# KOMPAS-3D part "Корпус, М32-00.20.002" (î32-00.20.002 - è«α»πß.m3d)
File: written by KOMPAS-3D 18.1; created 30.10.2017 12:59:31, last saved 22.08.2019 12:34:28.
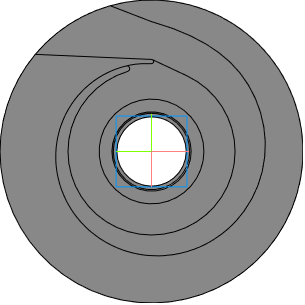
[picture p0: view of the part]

Document properties: Автор: Милов; Организация: Милов; Полное имя файла: D:\Magna\Магна Ins\Магна ins 32\Для Караби Магна 32\М32-00.20.002 - Корпус.m3d

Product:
- Part/product: Корпус  | designation М32-00.20.002  | pos. 0
    Материал: Полипропилен  ГОСТ 26996-86 (density 900 kg/m3)
    Масса: 1.66329
    Раздел спецификации: Детали
    Форматы листов документа: A3
    source file: М32-00.20.002 - Корпус.cdw

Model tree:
1. Эскиз:1
2. Операция выдавливания:1
     Расстояние 1 = 64
3. Эскиз:3  (with: Операция выдавливания:1)
4. Вырезать элемент выдавливания:1
     Расстояние 1 = 50
5. Эскиз:5  (with: Вырезать элемент выдавливания:1)
6. Операция выдавливания:2
     Расстояние 1 = 6.5
7. Эскиз:7  (with: Операция выдавливания:1)
8. Операция выдавливания:3
     Расстояние 1 = 32
9. Фаска:2  (with: Операция выдавливания:2)
     Угол = 45; Длина 1 = 1; Длина 2 = 1
10. Эскиз:13  (with: Операция выдавливания:1)
11. Вырезать элемент выдавливания:3
     Толщина стенки 2 = 5; Расстояние 1 = 5
12. Эскиз:14  (with: Операция выдавливания:3, Вырезать элемент выдавливания:3)
13. Операция выдавливания:6
     Расстояние 1 = 3
14. Эскиз:16  (with: Вырезать элемент выдавливания:3)
15. Операция выдавливания:7  (with: Операция выдавливания:1)
     Расстояние 2 = 59
16. Эскиз:17  (with: Операция выдавливания:1, Операция выдавливания:7, Вырезать элемент выдавливания:1)
17. Вырезать элемент выдавливания:4  (with: Вырезать элемент выдавливания:1)
     Расстояние 1 = 50
18. Скругление:1
     Радиус = 20
19. Эскиз:18  (with: Вырезать элемент выдавливания:3, Операция выдавливания:7)
20. Операция выдавливания:8  (with: Операция выдавливания:6)
     Расстояние 1 = 8
21. Эскиз:20  (with: Операция выдавливания:6, Операция выдавливания:8)
22. Операция выдавливания:10
     Расстояние 1 = 4
23. Эскиз:19  (with: Операция выдавливания:10, Операция выдавливания:3)
24. Операция выдавливания:9
     Расстояние 1 = 8
25. Эскиз:22  (with: Вырезать элемент выдавливания:1, Вырезать элемент выдавливания:4)
26. Операция выдавливания:12  (with: Операция выдавливания:1)
     Расстояние 1 = 50
27. Скругление:2  (with: Вырезать элемент выдавливания:1)
     Радиус = 20
28. Эскиз:24  (with: Вырезать элемент выдавливания:1, Фаска:2)
29. Операция выдавливания:13  (with: Операция выдавливания:2)
     Толщина стенки 1 = 2; Расстояние 1 = 6.5
30. Эскиз:26  (with: Операция выдавливания:2, Операция выдавливания:13)
31. Вырезать элемент выдавливания:6  (with: Эскиз:30, Вырезать элемент выдавливания:1, Операция выдавливания:9)  (labels: Магна Ins 32-L-3(1)-N; Корпус М32\Корпус\Корпус)
     Расстояние 1 = 1.5
32. Вырезать элемент вращения:2  (with: Операция выдавливания:3)
     Угол 1 = 360
33. Вырезать элемент выдавливания:10  (with: Операция выдавливания:9)
     Расстояние 1 = 9
34. Фаска:5  (with: Вырезать элемент выдавливания:10)
     Угол = 45; Длина 1 = 2; Длина 2 = 2
35. Эскиз:31  (with: Вырезать элемент вращения:2, Вырезать элемент выдавливания:10)
36. Элемент выдавливания:1  (with: Операция выдавливания:1)
37. Эскиз:32  (with: Операция выдавливания:1, Элемент выдавливания:1)
38. Элемент выдавливания:2  (with: Вырезать элемент выдавливания:1)
     Расстояние 2 = 50
39. Эскиз:34  (with: Вырезать элемент вращения:2, Элемент выдавливания:1)
40. Элемент выдавливания:3  (with: Операция выдавливания:6)  (labels: ..\М32-00.20.000 - Корпус.a3d; D:\Magna\Магна Ins\Магна ins 32\М32-00.20.000 - Корпус.a3d)
     Расстояние 1 = 6.5
41. Элемент выдавливания:4  (with: Вырезать элемент вращения:2, Вырезать элемент выдавливания:1)
42. Фаска:7  (with: Элемент выдавливания:3, Элемент выдавливания:4, Эскиз:36, Операция выдавливания:1, Операция выдавливания:3)
     Угол = 45; Длина 1 = 2; Длина 2 = 2
43. Элемент выдавливания:5
     Расстояние 2 = 8
44. Фаска:8  (with: Элемент выдавливания:5)
     Угол = 45; Длина 1 = 3; Длина 2 = 3
45. Эскиз:37  (with: Операция выдавливания:1, Элемент выдавливания:1)
46. Элемент выдавливания:6  (with: Вырезать элемент выдавливания:1)
     Расстояние 2 = 50
47. Эскиз:28
48. Операция выдавливания:14
     Расстояние 1 = 5
49. Сечение поверхностью:2  (labels: Полипропилен  ГОСТ 26996-86)

Referenced files in D:\Magna\Магна Ins\Магна ins 32\: М32-00.00.000 - Магна Ins 32-L-3(1)-N.a3d

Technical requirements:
  Gost Type A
